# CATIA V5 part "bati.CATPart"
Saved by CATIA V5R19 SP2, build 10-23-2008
Part number: bati
Bounding box of the stored display mesh (mm): x 0 to 200, y 0 to 530, z 0 to 200
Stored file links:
  C:\Users\Guillaume\Desktop\ETUDES\IFMA\S3\IAO\Projet IAO\ggaubert_1504\bati.CATPart
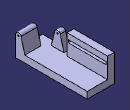
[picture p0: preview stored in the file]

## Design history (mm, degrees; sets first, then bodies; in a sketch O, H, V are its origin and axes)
Parameters
  entraxe_AF = 130 mm
  Longueur_A_debut_coulisse = 80 mm
Set1
  Plane1: type Offset, RefPlane xy-plane, Offset 400
Body1 (main body)
  Sketch1 on yz-plane, origin (0, 0, 0), H (0, 1, 0), V (0, 0, 1)
    point P1 (0, 0)
    line L1 (0, 0) -> (0, 150)
    arc A1 centre (20, 150) radius 20 from (0, 150) to (39.3185, 155.1764) cw
    point P3 (20, 150)
    line L2 (39.3185, 155.1764) -> (67.5004, 50)
    line L3 (67.5004, 50) -> (102.4996, 50)
    line L4 (102.4996, 50) -> (130.6815, 155.1764)
    arc A2 centre (150, 150) radius 20 from (130.6815, 155.1764) to (169.3185, 155.1764) cw
    point P8 (150, 150)
    line L5 (169.3185, 155.1764) -> (197.5004, 50)
    line L6 (197.5004, 50) -> (230, 50)
    line L7 (230, 50) -> (230, 200)
    line L8 (230, 200) -> (530, 200)
    line L9 (530, 200) -> (530, 0)
    point P14 (530, 0)
    line L10 (530, 0) -> (0, 0)
    angle L2 V = 15
    angle L4 V = 15
    radius A1 = 20
    radius A2 = 20
    distance L3 L10 = 50
    distance P3 L10 = 150
    distance P8 L10 = 150
    distance P8 P3 = 130 {= entraxe_AF}
    angle L5 L1 = 15
    distance L10 L6 = 50
    distance P8 L7 = 80 {= Longueur_A_debut_coulisse}
    distance L8 L10 = 200
    length L8 = 300
    coincidence: P1 H, P14 H, P1 O
    vertical: L1 V, L7 V, L9 V
    tangency: A1 L1, A2 L4, L5 A2, L2 A1
    horizontal: L3 H, L6 H, L8 H, L10 H
  Sketch2 on yz-plane, origin (0, 0, 0), H (0, 1, 0), V (0, 0, 1)
    circle A1 centre (20, 150) radius 5
    point P1 (20, 150)
    circle A2 centre (150, 150) radius 5
    point P2 (150, 150)
    reference projected arc E1 centre (20, 150) radius 20 from (39.3185, 155.1764) to (0, 150) ccw from Sketch1.A1
    reference projected arc E2 centre (150, 150) radius 20 from (169.3185, 155.1764) to (130.6815, 155.1764) ccw from Sketch1.A2
    line L1 (240, 160) -> (520, 160)
    line L2 (520, 160) -> (520, 140)
    line L3 (520, 140) -> (240, 140)
    line L4 (240, 140) -> (240, 160)
    reference projected line E3 (230, 200) -> (230, 50) from Sketch1.L7
    reference projected line E4 (530, 0) -> (530, 200) from Sketch1.L9
    radius A2 = 5
    radius A1 = 5
    distance L3 L1 = 20
    distance L4 E3 = 10
    distance L2 E4 = 10
    concentricity: P1 E1, P2 E2
    horizontal: L1 H, L3 H
    vertical: L2 V, L4 V
    equidistance: L3 L1 P2
  Pad1: profile Sketch1, direction (1, 0, 0), length 200
  Pocket1: profile Sketch2, direction (-1, 0, 0), up to end face of Pad1
  Sketch3 on Plane1, origin (0, 0, 400), H (1, 0, 0), V (0, 1, 0)
    line L1 (40, 197.5004) -> (200, 197.5004)
    line L2 (200, 197.5004) -> (200, 102.4996)
    line L3 (200, 102.4996) -> (40, 102.4996)
    line L4 (40, 102.4996) -> (40, 197.5004)
    reference projected line E1 (200, 172.4996) -> (200, 67.5004) from edge [face of Pad1 from Sketch1.L3 | end face of Pad1]
    reference projected line E2 (0, 102.4996) -> (200, 102.4996) from edge [face of Pad1 from Sketch1.L3 | face of Pad1 from Sketch1.L4]
    reference projected line E3 (0, 197.5004) -> (200, 197.5004) from edge [face of Pad1 from Sketch1.L5 | face of Pad1 from Sketch1.L6]
    line L5 (0, 67.5004) -> (80, 67.5004)
    line L6 (80, 67.5004) -> (80, 0)
    line L7 (80, 0) -> (0, 0)
    line L8 (0, 0) -> (0, 67.5004)
    reference projected line E4 (0, 67.5004) -> (200, 67.5004) from edge [face of Pad1 from Sketch1.L2 | face of Pad1 from Sketch1.L3]
    line L9 (50, 530) -> (200, 530)
    line L10 (200, 530) -> (200, 230)
    line L11 (200, 230) -> (50, 230)
    line L12 (50, 230) -> (50, 530)
    reference projected line E5 (0, 703.0719) -> (0, 403.0719) from edge [start face of Pad1 | face of Pad1 from Sketch1.L8]
    reference projected line E6 (200, 703.0719) -> (200, 403.0719) from edge [face of Pad1 from Sketch1.L8 | end face of Pad1]
    reference projected line E7 (0, 230) -> (200, 230) from edge [face of Pad1 from Sketch1.L7 | face of Pad1 from Sketch1.L8]
    reference projected line E8 (0, 530) -> (200, 530) from edge [face of Pad1 from Sketch1.L8 | face of Pad1 from Sketch1.L9]
    distance L4 V = 40
    distance L6 L8 = 80
    distance L12 E5 = 50
    horizontal: L1 H, L3 H, L5 H, L7 H, L9 H, L11 H
    vertical: L2 V, L4 V, L6 V, L8 V, L10 V, L12 V
    coincidence: L2 E1, E2 L3, L1 E3, L7 H, L5 E4, V L8, L10 E6, L11 E7, L9 E8
  Pocket2: profile Sketch3, direction (0, 0, -1), up to face of Pad1 from Sketch1.L6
